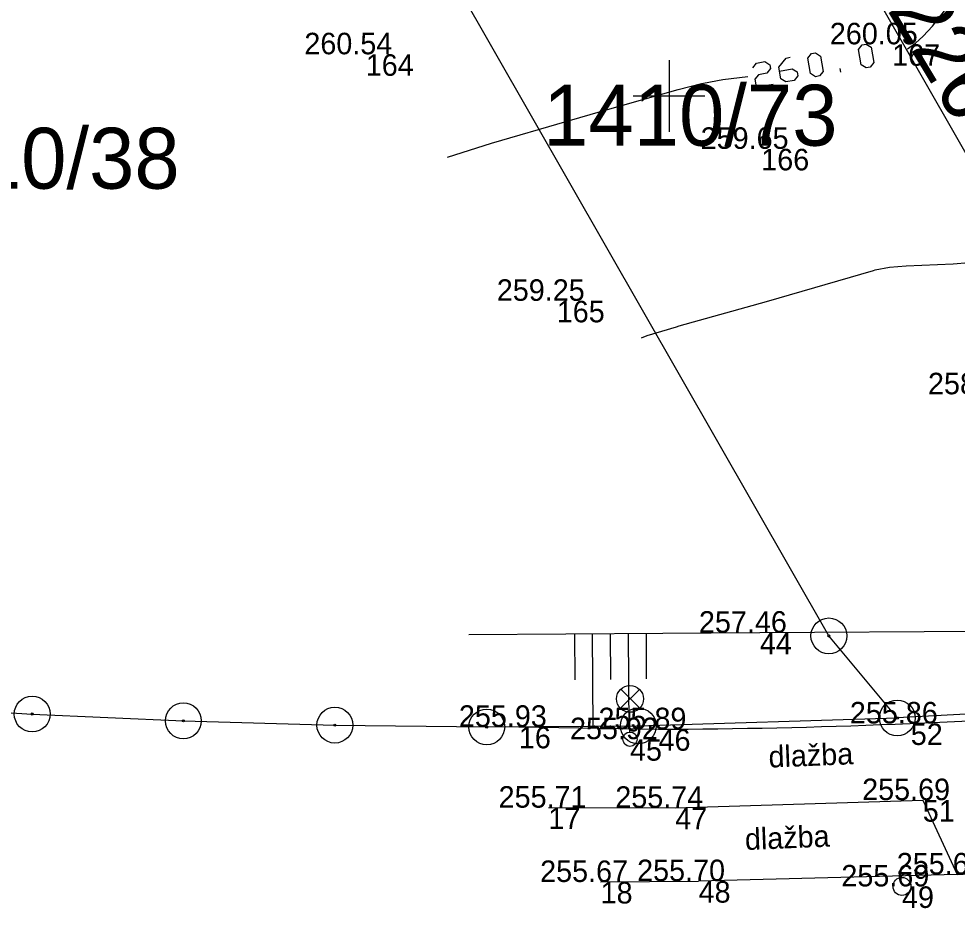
# Model space of a CAD drawing. Extents: x -771260 to -770828, y -1053564 to -1052811.
# Drawn here: x -770918.15 to -770891.96, y -1053372.67 to -1053347.85 of the extents above; entities that cross this region are included whole.
import ezdxf

# ---------------------------------------------------------------- set-up
doc = ezdxf.new("R2010")
doc.units = 0
for name, color, linetype in [('14_8_2023_dlazba', 7, 'Continuous'), ('14_8_2023_krizky', 7, 'Continuous'), ('14_8_2023_lampa', 7, 'Continuous'), ('14_8_2023_popis_povrchu', 7, 'Continuous'), ('14_8_2023_soupe', 7, 'Continuous'), ('14_8_2023_ter_hrana', 7, 'Continuous'), ('14_8_2023_ter_srafy', 7, 'Continuous'), ('14_8_2023_zamereny_bod', 7, 'Continuous'), ('14_8_2023_zamereny_bod_cislo', 7, 'Continuous'), ('14_8_2023_zamereny_bod_vyska', 7, 'Continuous'), ('18_8_2023_vrstevnice_po_1m', 7, 'Continuous'), ('18_8_2023_zamereny_bod', 7, 'Continuous'), ('18_8_2023_zamereny_bod_cislo', 7, 'Continuous'), ('18_8_2023_zamereny_bod_vyska', 7, 'Continuous'), ('25_3_2019_krizky_JTSK', 7, 'Continuous'), ('DKM_Hranice parcel', 7, 'Continuous'), ('DKM_Parcelní čísla', 7, 'Continuous'), ('DKM_Značky bodu BP', 7, 'Continuous')]:
    doc.layers.add(name, color=color, linetype=linetype)

# ---------------------------------------------------------------- blocks, each defined once
blk = doc.blocks.new('KRIZEK')
at = {"layer": '25_3_2019_krizky_JTSK'}
for p, q in [((0, 10), (0, -10)), ((-10, 0), (10, 0))]:
    blk.add_line(p, q, dxfattribs=at)

msp = doc.modelspace()

# ---------------------------------------------------------------- linework, layer by layer
at = {"layer": '14_8_2023_dlazba'}
for p, q in [((-770904.194, -1053367.607), (-770900.295, -1053367.674)), ((-770899.83, -1053369.867), (-770892.919, -1053369.653)), ((-770892.919, -1053369.653), (-770891.957, -1053371.726)), ((-770903.371, -1053369.863), (-770899.83, -1053369.867)), ((-770891.957, -1053371.726), (-770899.177, -1053371.913)), ((-770901.912, -1053371.937), (-770899.177, -1053371.913))]:
    msp.add_line(p, q, dxfattribs=at)
for centre, radius, start, end in [((-770900.926, -1053186.023), 181.652, 270.19912, 274.36998), ((-770897.564, -1053216.299), 155.529, 272.06585, 276.13275)]:
    msp.add_arc(centre, radius, start, end, dxfattribs=at)
at = {"layer": '14_8_2023_lampa'}
for p, q in [((-770901.356, -1053367.09), (-770900.828, -1053366.562)), ((-770900.82, -1053367.087), (-770901.348, -1053366.558)), ((-770901.092, -1053367.752), (-770901.092, -1053367.202))]:
    msp.add_line(p, q, dxfattribs=at)
for centre, radius in [((-770901.092, -1053366.827), 0.375), ((-770901.092, -1053367.952), 0.2)]:
    msp.add_circle(centre, radius, dxfattribs=at)
at = {"layer": '14_8_2023_soupe'}
msp.add_circle((-770893.499, -1053372.061), 0.25, dxfattribs=at)
at = {"layer": '14_8_2023_ter_hrana'}
for p, q in [((-770897.467, -1053364.98), (-770905.59, -1053365.036)), ((-770884.123, -1053364.905), (-770897.467, -1053364.98))]:
    msp.add_line(p, q, dxfattribs=at)
at = {"layer": '14_8_2023_ter_srafy'}
for p, q in [((-770901.145, -1053365.005), (-770901.126, -1053367.674)), ((-770900.645, -1053365.002), (-770900.636, -1053366.272)), ((-770902.645, -1053365.016), (-770902.636, -1053366.297)), ((-770902.145, -1053365.012), (-770902.126, -1053367.643)), ((-770901.645, -1053365.009), (-770901.636, -1053366.285))]:
    msp.add_line(p, q, dxfattribs=at)
at = {"layer": '14_8_2023_zamereny_bod'}
for p, q in [((-770897.467, -1053364.98), (-770897.467, -1053364.98)), ((-770904.194, -1053367.607), (-770904.194, -1053367.607)), ((-770893.254, -1053367.513), (-770893.254, -1053367.513)), ((-770900.295, -1053367.674), (-770900.295, -1053367.674)), ((-770901.092, -1053367.952), (-770901.092, -1053367.952)), ((-770892.919, -1053369.653), (-770892.919, -1053369.653)), ((-770903.371, -1053369.863), (-770903.371, -1053369.863)), ((-770899.83, -1053369.867), (-770899.83, -1053369.867)), ((-770891.957, -1053371.726), (-770891.957, -1053371.726)), ((-770901.912, -1053371.937), (-770901.912, -1053371.937)), ((-770899.177, -1053371.913), (-770899.177, -1053371.913)), ((-770893.499, -1053372.061), (-770893.499, -1053372.061))]:
    msp.add_line(p, q, dxfattribs=at)
at = {"layer": '18_8_2023_vrstevnice_po_1m'}
for points in [[(-770893.346, -1053348.689), (-770893.123, -1053348.53), (-770892.909, -1053348.337), (-770892.651, -1053348.052), (-770892.308, -1053347.623), (-770891.763, -1053346.908), (-770891.597, -1053346.714), (-770891.567, -1053346.679), (-770891.408, -1053346.444), (-770891.186, -1053346.175), (-770890.801, -1053345.799), (-770890.737, -1053345.736), (-770890.705, -1053345.705), (-770890.691, -1053345.697), (-770890.655, -1053345.676), (-770890.472, -1053345.54), (-770890.049, -1053345.143), (-770890.017, -1053345.112)], [(-770892.651, -1053348.052), (-770892.651, -1053348.052)], [(-770892.909, -1053348.337), (-770892.909, -1053348.337)], [(-770894.502, -1053349.22), (-770894.638, -1053349.133), (-770894.712, -1053348.704), (-770894.613, -1053348.577), (-770894.495, -1053348.556), (-770894.359, -1053348.643), (-770894.284, -1053349.072), (-770894.384, -1053349.2), (-770894.502, -1053349.22)], [(-770893.346, -1053348.689), (-770893.346, -1053348.689)], [(-770893.123, -1053348.53), (-770893.123, -1053348.53)], [(-770896.917, -1053349.306), (-770896.563, -1053349.245), (-770896.426, -1053349.332), (-770896.408, -1053349.439), (-770896.507, -1053349.567), (-770896.743, -1053349.607), (-770896.88, -1053349.521), (-770896.935, -1053349.199), (-770896.736, -1053348.944), (-770896.619, -1053348.923)], [(-770895.917, -1053349.465), (-770896.054, -1053349.378), (-770896.128, -1053348.949), (-770896.029, -1053348.821), (-770895.911, -1053348.801), (-770895.774, -1053348.888), (-770895.7, -1053349.317), (-770895.799, -1053349.444), (-770895.917, -1053349.465)], [(-770897.662, -1053349.214), (-770897.562, -1053349.086), (-770897.326, -1053349.045), (-770897.19, -1053349.132), (-770897.171, -1053349.24), (-770897.271, -1053349.367), (-770897.507, -1053349.408), (-770897.606, -1053349.536), (-770897.569, -1053349.75), (-770897.097, -1053349.669)], [(-770895.21, -1053349.342), (-770895.228, -1053349.235)], [(-770906.189, -1053351.707), (-770904.957, -1053351.32), (-770902.847, -1053350.703), (-770901.851, -1053350.421), (-770899.744, -1053349.822), (-770899.092, -1053349.658), (-770899.042, -1053349.646), (-770898.501, -1053349.547), (-770897.802, -1053349.459)], [(-770898.501, -1053349.547), (-770898.501, -1053349.547)], [(-770899.042, -1053349.646), (-770899.042, -1053349.646)], [(-770899.744, -1053349.822), (-770899.744, -1053349.822)], [(-770902.847, -1053350.703), (-770902.847, -1053350.703)], [(-770904.957, -1053351.32), (-770904.957, -1053351.32)], [(-770906.189, -1053351.707), (-770906.189, -1053351.707)], [(-770900.774, -1053356.753), (-770900.609, -1053356.686), (-770899.791, -1053356.444), (-770899.715, -1053356.421), (-770897.28, -1053355.74), (-770894.294, -1053354.871), (-770894.246, -1053354.857), (-770893.85, -1053354.78), (-770893.387, -1053354.74), (-770892.071, -1053354.686), (-770891.633, -1053354.654)], [(-770893.85, -1053354.78), (-770893.85, -1053354.78)], [(-770893.387, -1053354.74), (-770893.387, -1053354.74)], [(-770892.071, -1053354.686), (-770892.071, -1053354.686)], [(-770894.246, -1053354.857), (-770894.246, -1053354.857)], [(-770897.28, -1053355.74), (-770897.28, -1053355.74)], [(-770899.715, -1053356.421), (-770899.715, -1053356.421)], [(-770900.774, -1053356.753), (-770900.774, -1053356.753)], [(-770900.609, -1053356.686), (-770900.609, -1053356.686)]]:
    msp.add_lwpolyline(points, dxfattribs=at)
at = {"layer": '18_8_2023_zamereny_bod'}
for p, q in [((-770893.773, -1053348.561), (-770893.773, -1053348.561)), ((-770908.468, -1053348.839), (-770908.468, -1053348.839)), ((-770897.428, -1053351.478), (-770897.428, -1053351.478)), ((-770903.136, -1053355.719), (-770903.136, -1053355.719))]:
    msp.add_line(p, q, dxfattribs=at)
at = {"layer": 'DKM_Hranice parcel'}
for points in [[(-770893.63, -1053367.36), (-770895.54, -1053365.07), (-770911.11, -1053337.86), (-770914.09, -1053331.12)], [(-770902.17, -1053333.34), (-770887.29, -1053359.35), (-770881.36, -1053366.49)], [(-770929.7, -1053366.29), (-770926.23, -1053366.64), (-770922.01, -1053366.98), (-770917.78, -1053367.25), (-770913.56, -1053367.44), (-770909.33, -1053367.56), (-770905.09, -1053367.61), (-770900.86, -1053367.58), (-770893.63, -1053367.36)], [(-770881.36, -1053366.49), (-770884.64, -1053366.79), (-770889.26, -1053367.12), (-770893.63, -1053367.36)]]:
    msp.add_lwpolyline(points, dxfattribs=at)
at = {"layer": 'DKM_Značky bodu BP'}
for centre, radius in [((-770895.54, -1053365.07), 0.5), ((-770895.54, -1053365.07), 0.0303), ((-770917.78, -1053367.25), 0.5), ((-770913.56, -1053367.44), 0.5), ((-770909.33, -1053367.56), 0.5), ((-770900.86, -1053367.58), 0.5), ((-770893.63, -1053367.36), 0.5), ((-770917.78, -1053367.25), 0.0303), ((-770905.09, -1053367.61), 0.5), ((-770893.63, -1053367.36), 0.0303), ((-770913.56, -1053367.44), 0.0303), ((-770909.33, -1053367.56), 0.0303), ((-770905.09, -1053367.61), 0.0303), ((-770900.86, -1053367.58), 0.0303)]:
    msp.add_circle(centre, radius, dxfattribs=at)

# ---------------------------------------------------------------- block references
at = {"layer": '14_8_2023_krizky', "xscale": 0.1, "yscale": 0.10000000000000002}
msp.add_blockref('KRIZEK', (-770900, -1053350), dxfattribs=at)

# ---------------------------------------------------------------- texts
at = {"layer": '14_8_2023_popis_povrchu'}
for p in [(-770897.213, -1053368.746), (-770897.873, -1053371.046)]:
    msp.add_text('dlažba', height=0.6, rotation=2.3434, dxfattribs=at).set_placement(p)
at = {"layer": '14_8_2023_zamereny_bod_cislo'}
for s, p in [('44', (-770897.467, -1053365.58)), ('16', (-770904.194, -1053368.207)), ('52', (-770893.254, -1053368.113)), ('46', (-770900.295, -1053368.274)), ('45', (-770901.092, -1053368.552)), ('51', (-770892.919, -1053370.253)), ('17', (-770903.371, -1053370.463)), ('47', (-770899.83, -1053370.467)), ('18', (-770901.912, -1053372.537)), ('48', (-770899.177, -1053372.513)), ('49', (-770893.499, -1053372.661))]:
    msp.add_text(s, height=0.6, dxfattribs=at).set_placement(p)
at = {"layer": '14_8_2023_zamereny_bod_vyska'}
for s, p in [('257.46 ', (-770899.167, -1053364.98)), ('255.93 ', (-770905.868, -1053367.607)), ('255.89 ', (-770901.971, -1053367.674)), ('255.86 ', (-770894.954, -1053367.513)), ('255.92 ', (-770902.766, -1053367.952)), ('255.69 ', (-770894.611, -1053369.653)), ('255.71 ', (-770904.759, -1053369.863)), ('255.74 ', (-770901.502, -1053369.867)), ('255.67 ', (-770893.645, -1053371.726)), ('255.67 ', (-770903.6, -1053371.937)), ('255.70 ', (-770900.893, -1053371.913)), ('255.69 ', (-770895.191, -1053372.061))]:
    msp.add_text(s, height=0.6, dxfattribs=at).set_placement(p)
at = {"layer": '18_8_2023_zamereny_bod_cislo'}
for s, p in [('167', (-770893.773, -1053349.161)), ('164', (-770908.468, -1053349.439)), ('166', (-770897.428, -1053352.078)), ('165', (-770903.136, -1053356.319))]:
    msp.add_text(s, height=0.6, dxfattribs=at).set_placement(p)
at = {"layer": '18_8_2023_zamereny_bod_vyska'}
for s, p in [('260.05 ', (-770895.513, -1053348.561)), ('260.54 ', (-770910.182, -1053348.839)), ('259.65 ', (-770899.119, -1053351.478)), ('259.25 ', (-770904.81, -1053355.719)), ('258.34 ', (-770892.773, -1053358.327))]:
    msp.add_text(s, height=0.6, dxfattribs=at).set_placement(p)
at = {"layer": 'DKM_Parcelní čísla'}
msp.add_text('1410/226', height=1.7, rotation=301, dxfattribs=at).set_placement((-770896.86, -1053342.711))
for s, p in [('1410/73', (-770903.516, -1053351.39)), ('1410/38', (-770921.88, -1053352.59))]:
    msp.add_text(s, height=1.7, dxfattribs=at).set_placement(p)

doc.saveas('drawing.dxf')
